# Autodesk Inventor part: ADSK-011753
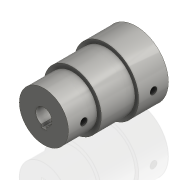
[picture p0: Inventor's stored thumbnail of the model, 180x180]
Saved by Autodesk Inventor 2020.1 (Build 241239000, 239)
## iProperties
Created: 1999-12
Part Number: ADSK-011753
Material: Aluminum
Document SubType Name: Modeling
Designer: tgregory
Density: 2.71 g/cm^3
Appearance: Steel
Mass: 492.764 g
Surface Area: 296.708 cm^2
Volume: 181.832 cm^3
Control State: 0
Master: False
Checked Out: False
Shininess: 0.0
Length Units: 11269
Angle Units: 11279
Time Units: 11290
Mass Units: 11283
Length Display Precision: 3
Angle Display Precision: 2
Compacted: True
Dimensions: 63x63x90 mm
Mass: 0,493 kg
DocNumber: ADSK-011753.ipt
Folder: 01 - Themengebiete\Simplification\01 - Packaging machine\
VDS_Category: 3D Komponenten
Density: 0.0
Volumn: 0.0
Area: 0.0
PropertySet Name: Model Information
Author: tgregory
Revision Number: -
Title: clutch
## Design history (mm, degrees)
node "Solide1"
  node "Extrusion1" dims "d1" = 90, "d2" = 0
  node "Extrusion2" dims "d4" = 28, "d5" = 0
  node "Extrusion4" dims "d10" = 35.0012, "d11" = 0
  node "Extrusion7" dims "d27" = 29, "d28" = 0
  node "Extrusion8" dims "d30" = 35.0012, "d31" = 0
  node "Hole1" dims "d20" = 6.647, "d21" = 9.525, "d22" = 6.35, "d23" = 60 deg, "d24" = 22.2, "d25" = 118 deg, "d57" = 16
  node "Extrusion10" dims "d44" = 19.9898, "d45" = 0
  node "Extrusion11" dims "d49" = 4.7625, "d50" = 0
  node "Extrusion12" dims "d55" = 3, "d56" = 0
sketch "Sketch1"
  geometry: C1 r 28 at (0, 0)
  constraints: 1 centre point
  dimensions: "d0" = 56 diameter of C1
sketch "Sketch2"
  geometry: C1 r 28 at (0, 0) reference; C2 r 24 at (0, 0)
  constraints: 1 centre point, 1 coincident
  dimensions: "d3" = 48 diameter of C2
fillet "Rundung1"
workplane "Work Plane1"
sketch "Sketch7"
  geometry: L1 (24, 90)-(-24, 90) reference; L2 (31.496, 0)-(31.496, 29) reference; 3 further points
  constraints: 1 horizontal alignment, 1 midpoint
  dimensions: "d18" = 15 distance from line of point (0.014, 75) L1
workplane "Work Plane3"
workplane "Work Plane4"
sketch "Sketch14"
  geometry: L1 (0, -90)-(0, -65); L2 (3, -90)-(3, -65); L3 (-3, -90)-(-3, -65); L4 (3, -90)-(3, -65); L5 (3, -65)-(-3, -65); L6 (-3, -65)-(-3, -90); L7 (-3, -90)-(3, -90); L8 (31.496, -90)-(-31.496, -90) reference; 1 further point
  constraints: 14 end point, 3 collinear, 3 midpoint, 3 perpendicular, 1 point on line
  dimensions: "d59" = 6 distance between parallel lines of L3 L2; "d60" = 25 distance of L2.start L2.end
node "Corps solides"
node "Corps surfaciques"
sketch "Sketch4"
  geometry: C1 r 24 at (0, 0) reference; C2 r 7.938 at (0, 0)
  constraints: 1 centre point, 1 coincident
  dimensions: "d9" = 15.875 diameter of C2
sketch "Sketch8"
  geometry: C1 r 28 at (0, 0) reference; C2 r 31.496 at (0, 0)
  constraints: 1 centre point, 1 coincident
  dimensions: "d26" = 62.992 diameter of C2
sketch "Sketch9"
  geometry: C1 r 31.496 at (0, 0) reference; C2 r 12.7 at (0, 0)
  constraints: 1 centre point, 1 coincident
  dimensions: "d29" = 25.4 diameter of C2
sketch "Sketch12"
  geometry: C1 r 12.7 at (0, 0) reference; C2 r 14.986 at (0, 0)
  constraints: 1 centre point, 1 coincident
  dimensions: "d43" = 29.972 diameter of C2
sketch "Sketch13"
  geometry: L1 (24, 0)-(-24, 0) reference; L2 (0, 0)-(0, -34.869); L3 (21.662, -25.4)-(-20.966, -25.4); L4 (2.381, 0)-(2.381, -34.869); L5 (-2.381, 0)-(-2.381, -34.869); L6 (-2.381, 0)-(-2.381, -25.4); L7 (-2.381, -25.4)-(2.381, -25.4); L8 (2.381, -25.4)-(2.381, 0); L9 (-2.381, 0)-(2.381, 0)
  constraints: 16 end point, 4 point on line, 2 collinear, 2 perpendicular, 1 midpoint
  dimensions: "d46" = 25.4 distance between parallel lines of L3 L1; "d47" = 2.38125 distance between parallel lines of L4 L2; "d48" = 2.38125 distance between parallel lines of L5 L2 (= d47)
other parameters: "d51" = -4.7625
